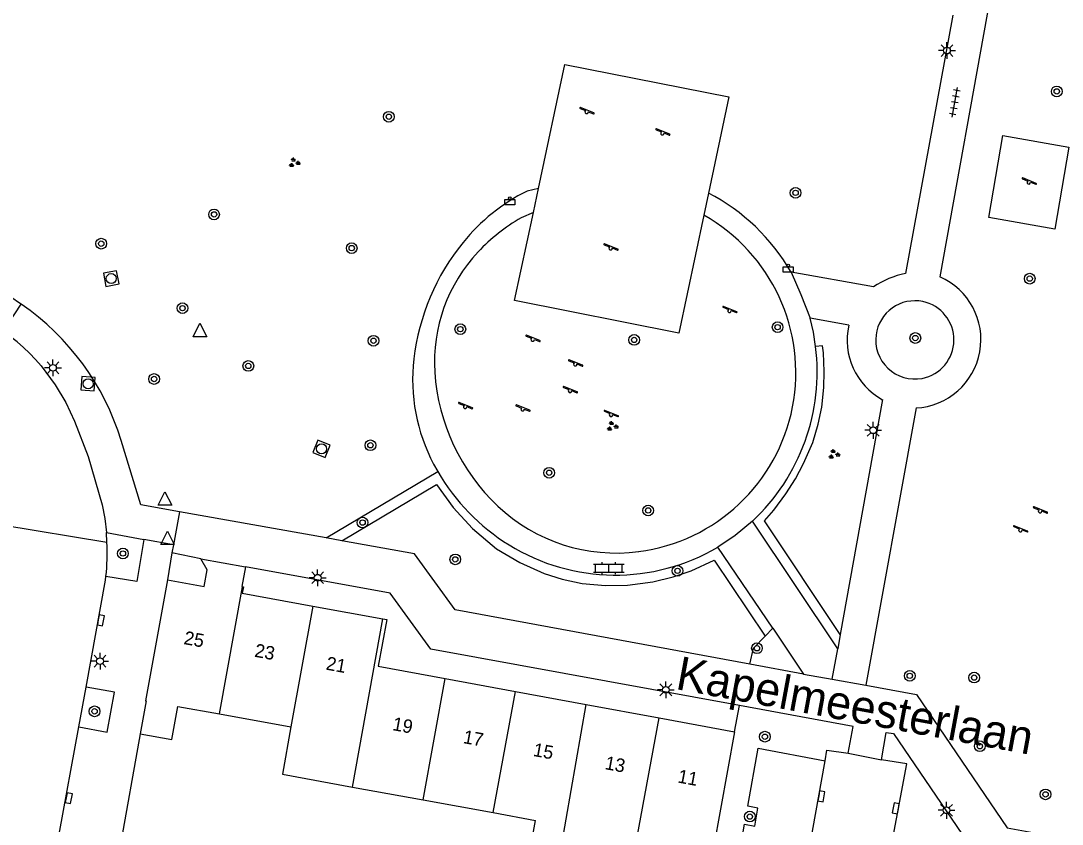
# Model space of a CAD drawing. Extents: x 133000 to 136000, y 400500 to 403500.
# Drawn here: x 133622.8 to 133700.5, y 400549.9 to 400609.9 of the extents above; entities that cross this region are included whole.
import ezdxf

# ---------------------------------------------------------------- set-up
doc = ezdxf.new("R2010")
doc.units = 0
for name, color, linetype in [('gg-afsc-muur', 7, 'Continuous'), ('gg-anno-huisnummerreeks BGT', 7, 'Continuous'), ('gg-anno-openbare ruimte label', 7, 'Continuous'), ('gg-bbg-gedigitaliseerde bebouwing', 7, 'Continuous'), ('gg-bbg-hoofdgebouw', 7, 'Continuous'), ('gg-bbg-tussenscheiding', 7, 'Continuous'), ('gg-knt-onverhard', 7, 'Continuous'), ('gg-knt-verharding', 7, 'Continuous'), ('gg-knt-verharding nz', 7, 'Continuous'), ('gt-grn-groengrens', 7, 'Continuous'), ('gt-grn-weggrens', 7, 'Continuous'), ('gt-symb-afvalbak', 7, 'Continuous'), ('gt-symb-boom', 7, 'Continuous'), ('gt-symb-groenvak', 7, 'Continuous'), ('gt-symb-klinker verharding', 7, 'Continuous'), ('gt-symb-kolk', 7, 'Continuous'), ('gt-symb-lichtmast', 7, 'Continuous'), ('gt-symb-rioolschacht', 7, 'Continuous'), ('gt-symb-speelvoorziening', 7, 'Continuous'), ('gt-symb-tegel verharding', 7, 'Continuous'), ('gt-symb-waterafsluiter', 7, 'Continuous')]:
    doc.layers.add(name, color=color, linetype=linetype)

# ---------------------------------------------------------------- blocks, each defined once
blk = doc.blocks.new('gt0-BOOM')
at = {"layer": 'gt-symb-boom'}
for radius in [0.4, 0.2]:
    blk.add_circle((0, 0), radius, dxfattribs=at)
blk = doc.blocks.new('gt0-SV')
at = {"layer": 'gt-symb-speelvoorziening'}
for p, q in [((-0.477, 0.255), (-0.08, 0.096)), ((0.542, -0.076), (-0.449, 0.324)), ((0.125, 0.014), (0.515, -0.143))]:
    blk.add_line(p, q, dxfattribs=at)
for centre, radius, start, end in [((-0.466, 0.291), 0.0369, 63.6251, 252.66016), ((-0.002, -0.005), 0.128, 127.68665, 8.59861), ((0.531, -0.111), 0.0363, 243.50852, 72.54358)]:
    blk.add_arc(centre, radius, start, end, dxfattribs=at)
blk = doc.blocks.new('gt0-LMAST')
at = {"layer": 'gt-symb-lichtmast'}
for p, q in [((-0.182, 0.173), (-0.447, 0.438)), ((-0.005, 0.246), (-0.005, 0.621)), ((0.172, 0.173), (0.437, 0.438)), ((-0.255, -0.004), (-0.63, -0.004)), ((-0.182, -0.181), (-0.447, -0.446)), ((-0.005, -0.254), (-0.005, -0.629)), ((0.437, -0.446), (0.172, -0.181)), ((0.245, -0.004), (0.62, -0.004))]:
    blk.add_line(p, q, dxfattribs=at)
blk.add_circle((-0.005, -0.004), 0.25, dxfattribs=at)
blk = doc.blocks.new('gt0-TEG1')
at = {"layer": 'gt-symb-tegel verharding'}
for p, q in [((-1.125, 0), (1.125, 0)), ((-0.9, -0.25), (-0.9, 0.25)), ((-0.45, -0.25), (-0.45, 0.25)), ((0, -0.25), (0, 0.25)), ((0.45, -0.25), (0.45, 0.25)), ((0.9, -0.25), (0.9, 0.25))]:
    blk.add_line(p, q, dxfattribs=at)
blk = doc.blocks.new('gt0-GRVAK')
at = {"layer": 'gt-symb-groenvak'}
for p, q in [((-0.11, 0.189), (-0.228, 0.24)), ((-0.182, 0.153), (0.088, 0.153)), ((-0.091, 0.211), (-0.156, 0.322)), ((-0.047, 0.214), (-0.047, 0.393)), ((-0.004, 0.211), (0.061, 0.322)), ((0.015, 0.189), (0.133, 0.24)), ((0.262, -0.052), (0.197, 0.059)), ((0.305, -0.049), (0.305, 0.13)), ((0.349, -0.052), (0.414, 0.059)), ((-0.245, -0.228), (-0.363, -0.177)), ((-0.318, -0.264), (-0.047, -0.264)), ((-0.226, -0.206), (-0.291, -0.095)), ((-0.183, -0.203), (-0.183, -0.024)), ((-0.139, -0.206), (-0.074, -0.095)), ((-0.12, -0.228), (-0.002, -0.177)), ((0.243, -0.074), (0.125, -0.023)), ((0.17, -0.11), (0.441, -0.11)), ((0.368, -0.074), (0.486, -0.023))]:
    blk.add_line(p, q, dxfattribs=at)
blk = doc.blocks.new('gt0-KOLK')
at = {"layer": 'gt-symb-kolk'}
blk.add_lwpolyline([(0, 0), (0.375, 0), (0.375, 0.4), (-0.375, 0.4), (-0.375, 0), (0, 0)], dxfattribs=at)
blk = doc.blocks.new('gt0-ABAK')
at = {"layer": 'gt-symb-afvalbak'}
blk.add_lwpolyline([(0.375, -0.5), (-0.375, -0.5), (-0.375, -0.1), (0.375, -0.1)], close=True, dxfattribs=at)
blk.add_circle((0, 0), 0.1, dxfattribs=at)
blk = doc.blocks.new('gt0-KL1')
at = {"layer": 'gt-symb-klinker verharding'}
for p, q in [((-1.15, 0.3), (1.15, 0.3)), ((-1, -0.3), (-1, 0.3)), ((-0.5, 0.3), (-0.5, 0.45)), ((0, -0.3), (0, 0.3)), ((0.5, 0.3), (0.5, 0.45)), ((1, -0.3), (1, 0.3)), ((-1.15, -0.3), (1.15, -0.3)), ((-0.5, -0.45), (-0.5, -0.3)), ((0.5, -0.45), (0.5, -0.3))]:
    blk.add_line(p, q, dxfattribs=at)
blk = doc.blocks.new('gt0-RS')
at = {"layer": 'gt-symb-rioolschacht'}
blk.add_lwpolyline([(-0.5, -0.5), (0.5, -0.5), (0.5, 0.5), (-0.5, 0.5)], close=True, dxfattribs=at)
blk.add_circle((0, 0), 0.375, dxfattribs=at)
blk = doc.blocks.new('gt0-WAFSL')
at = {"layer": 'gt-symb-waterafsluiter'}
for p, q in [((-0.5, -0.333), (0, 0.667)), ((0, 0.667), (0.5, -0.333)), ((0.5, -0.333), (-0.5, -0.333))]:
    blk.add_line(p, q, dxfattribs=at)

msp = doc.modelspace()

# ---------------------------------------------------------------- linework, layer by layer
at = {"layer": 'gg-afsc-muur'}
for p, q in [((133634.08, 400570.17), (133633.76, 400568.16)), ((133631.709, 400556.671), (133630.137, 400547.881))]:
    msp.add_line(p, q, dxfattribs=at)
at = {"layer": 'gg-bbg-gedigitaliseerde bebouwing'}
for p, q in [((133634.532, 400558.708), (133637.624, 400558.157)), ((133637.624, 400558.157), (133642.966, 400557.205)), ((133647.558, 400552.7), (133652.819, 400551.743)), ((133652.819, 400551.743), (133658.058, 400550.79)), ((133658.058, 400550.79), (133661.212, 400550.216))]:
    msp.add_line(p, q, dxfattribs=at)
msp.add_lwpolyline([(133642.966, 400557.205), (133642.335, 400553.661), (133647.558, 400552.7)], dxfattribs=at)
at = {"layer": 'gg-bbg-hoofdgebouw'}
for p, q in [((133636.23, 400569.73), (133639.58, 400569.14)), ((133644.605, 400566.205), (133649.818, 400565.263)), ((133654.474, 400560.799), (133659.734, 400559.833)), ((133659.734, 400559.833), (133665.008, 400558.864)), ((133665.008, 400558.864), (133670.442, 400557.866)), ((133670.442, 400557.866), (133676.08, 400556.83)), ((133676.08, 400556.83), (133674.467, 400547.959))]:
    msp.add_line(p, q, dxfattribs=at)
for points in [[(133633.76, 400568.16), (133636.48, 400567.66), (133636.71, 400568.91), (133636.23, 400569.73)], [(133639.58, 400569.14), (133639.3, 400567.651), (133639.358, 400567.64)], [(133633.76, 400568.16), (133632.11, 400559.14), (133632.159, 400559.131), (133631.709, 400556.671)], [(133639.358, 400567.64), (133639.41, 400567.63), (133639.32, 400567.16), (133644.605, 400566.205)], [(133649.818, 400565.263), (133650.11, 400565.21), (133649.46, 400561.72), (133654.474, 400560.799)], [(133631.709, 400556.671), (133634.08, 400556.237), (133634.532, 400558.708)], [(133662.766, 400546.131), (133660.552, 400546.528), (133661.212, 400550.216)]]:
    msp.add_lwpolyline(points, dxfattribs=at)
at = {"layer": 'gg-bbg-tussenscheiding'}
for p, q in [((133637.624, 400558.157), (133639.358, 400567.64)), ((133644.605, 400566.205), (133642.966, 400557.205)), ((133647.558, 400552.7), (133649.818, 400565.263)), ((133652.819, 400551.743), (133654.474, 400560.799)), ((133658.058, 400550.79), (133659.734, 400559.833)), ((133662.766, 400546.131), (133665.008, 400558.864)), ((133668.78, 400548.84), (133670.442, 400557.866))]:
    msp.add_line(p, q, dxfattribs=at)
at = {"layer": 'gg-knt-onverhard'}
for points in [[(133661.433, 400597.346), (133663.401, 400606.609), (133675.642, 400604.196), (133674.122, 400597.016)], [(133673.773, 400595.365), (133671.909, 400586.559), (133659.658, 400588.991), (133661.055, 400595.566)]]:
    msp.add_lwpolyline(points, dxfattribs=at)
at = {"layer": 'gg-knt-verharding'}
for p, q in [((133697.797, 400626.302), (133691.382, 400590.767)), ((133692.36, 400610.29), (133688.836, 400591.028)), ((133661.433, 400597.346), (133660.585, 400597.162)), ((133661.055, 400595.566), (133661.433, 400597.346)), ((133674.122, 400597.016), (133673.773, 400595.365)), ((133661.055, 400595.566), (133660.137, 400595.174)), ((133686.44, 400590.013), (133680.286, 400591.116)), ((133621.936, 400587.354), (133622.834, 400588.725)), ((133684.597, 400587.156), (133681.71, 400587.677)), ((133687.12, 400581.603), (133683.962, 400564.083)), ((133689.616, 400580.985), (133685.88, 400560.29)), ((133653.61, 400576.782), (133653.917, 400576.232)), ((133645.586, 400571.286), (133634.647, 400573.238)), ((133683.77, 400563.02), (133677.41, 400572.54)), ((133629.232, 400570.974), (133629.186, 400571.683)), ((133629.186, 400571.683), (133631.988, 400571.176)), ((133646.761, 400571.076), (133645.586, 400571.286)), ((133678.925, 400564.545), (133674.83, 400570.61)), ((133636.23, 400569.73), (133634.08, 400570.17)), ((133678.925, 400564.545), (133681.23, 400561.13)), ((133683.962, 400564.083), (133683.77, 400563.02)), ((133681.23, 400561.13), (133677.22, 400561.869)), ((133627.131, 400557.189), (133627.672, 400560.162)), ((133625.674, 400549.187), (133627.131, 400557.189)), ((133677.836, 400555.603), (133682.827, 400554.662)), ((133684.56, 400555.24), (133687.05, 400554.72))]:
    msp.add_line(p, q, dxfattribs=at)
for points in [[(133695.055, 400595.183), (133696.094, 400601.301), (133701.016, 400600.453), (133699.977, 400594.335), (133695.055, 400595.183)], [(133680.286, 400591.116), (133681.018, 400589.437), (133681.71, 400587.677)], [(133682.123, 400585.582), (133681.953, 400586.638), (133681.71, 400587.677)], [(133624.311, 400584.13), (133625.356, 400582.715), (133626.165, 400581.399), (133626.804, 400579.989), (133627.838, 400577.361), (133628.883, 400573.765), (133629.066, 400572.729), (133629.186, 400571.683)], [(133634.647, 400573.238), (133631.77, 400573.751), (133630.289, 400578.564)], [(133677.41, 400572.54), (133676.112, 400571.476), (133674.83, 400570.61)], [(133631.988, 400571.176), (133631.448, 400568.038), (133629.154, 400568.402)], [(133677.22, 400561.869), (133655.23, 400565.92), (133652.18, 400570.11), (133646.761, 400571.076)], [(133676.442, 400558.775), (133653.41, 400563), (133650.38, 400567.17), (133639.58, 400569.14)], [(133627.672, 400560.162), (133629.126, 400568.146), (133629.154, 400568.402)], [(133627.131, 400557.189), (133629.246, 400556.804), (133629.795, 400559.776), (133627.672, 400560.162)], [(133685.88, 400560.29), (133689.64, 400559.61), (133696.42, 400549.65), (133718.848, 400545.574)], [(133684.56, 400555.24), (133684.92, 400557.22), (133676.442, 400558.775)], [(133687.05, 400554.72), (133687.4, 400556.78), (133687.94, 400556.69), (133694.62, 400546.86)], [(133676.417, 400547.599), (133676.823, 400549.932), (133677.584, 400549.78), (133677.808, 400551.129), (133677.062, 400551.267), (133677.836, 400555.603)], [(133682.827, 400554.662), (133682.97, 400555.45), (133684.56, 400555.24)], [(133687.39, 400546.213), (133688.93, 400554.42), (133687.05, 400554.72)]]:
    msp.add_lwpolyline(points, dxfattribs=at)
for centre, radius, start, end in [((133667.054, 400584.197), 14.49, 116.5163, 140.91437), ((133667.202, 400583.616), 15.082, 29.82141, 62.68583), ((133667.28, 400582.889), 14.21, 120.17568, 136.7059), ((133667.177, 400583.622), 13.468, 277.41282, 60.67764), ((133668.92, 400582.676), 16.897, 140.90051, 173.31017), ((133665.662, 400584.414), 11.987, 136.70653, 183.6492), ((133690.293, 400584.253), 6.93, 102.13715, 123.78009), ((133611.924, 400572.894), 19.226, 55.4287, 63.35378), ((133689.354, 400586.083), 5.105, 272.94586, 66.58674), ((133613.564, 400575.122), 14.023, 39.97011, 81.01857), ((133611.929, 400572.909), 19.211, 17.11988, 55.41419), ((133689.527, 400586.06), 2.92, 78.35316, 172.33223), ((133689.526, 400586.061), 2.919, 280.64289, 78.33685), ((133689.514, 400586.04), 5.042, 167.21803, 241.65122), ((133689.526, 400586.061), 2.919, 172.33838, 280.64136), ((133666.979, 400583.682), 15.263, 313.11228, 7.15095), ((133665.503, 400583.078), 13.457, 173.3153, 207.89409), ((133668.682, 400584.605), 15.013, 183.64169, 226.80142), ((133667.534, 400584.176), 15.765, 210.25844, 238.2653), ((133667.249, 400583.079), 12.92, 226.80569, 277.41048), ((133611.652, 400570.22), 17.596, 354.06982, 2.45607), ((133667.167, 400583.594), 15.077, 238.28917, 300.54937)]:
    msp.add_arc(centre, radius, start, end, dxfattribs=at)
at = {"layer": 'gg-knt-verharding nz'}
msp.add_line((133679.271, 400534.991), (133682.827, 400554.662), dxfattribs=at)
at = {"layer": 'gt-grn-groengrens'}
for p, q in [((133645.586, 400571.286), (133653.917, 400576.232)), ((133678.367, 400563.966), (133678.925, 400564.545)), ((133676.08, 400556.83), (133676.442, 400558.775))]:
    msp.add_line(p, q, dxfattribs=at)
for points in [[(133683.962, 400564.083), (133678.304, 400572.552), (133679.004, 400573.35), (133679.9, 400574.576), (133680.614, 400575.705), (133681.22, 400576.831), (133681.914, 400578.411), (133682.322, 400579.778), (133682.578, 400581.032), (133682.745, 400582.518), (133682.772, 400583.711), (133682.715, 400585.094), (133682.641, 400585.624), (133682.123, 400585.582)], [(133646.761, 400571.076), (133653.822, 400575.268), (133655.061, 400573.554), (133656.511, 400571.985), (133658.301, 400570.481), (133660.034, 400569.443), (133661.873, 400568.641), (133663.211, 400568.21), (133664.708, 400567.88), (133666.441, 400567.738), (133668.092, 400567.762), (133669.978, 400568.01), (133671.493, 400568.376), (133672.837, 400568.836), (133674.548, 400569.623), (133678.367, 400563.966)], [(133677.22, 400561.869), (133677.489, 400563.054), (133678.367, 400563.966)]]:
    msp.add_lwpolyline(points, dxfattribs=at)
at = {"layer": 'gt-grn-weggrens'}
for p, q in [((133634.647, 400573.238), (133634.191, 400570.769)), ((133621.386, 400572.275), (133629.232, 400570.974)), ((133634.191, 400570.769), (133631.988, 400571.176)), ((133634.191, 400570.769), (133634.08, 400570.17)), ((133683.359, 400560.745), (133683.77, 400563.02)), ((133681.23, 400561.13), (133683.359, 400560.745)), ((133683.359, 400560.745), (133685.88, 400560.29))]:
    msp.add_line(p, q, dxfattribs=at)

# ---------------------------------------------------------------- block references
at = {"layer": 'gt-symb-afvalbak'}
for p in [(133659.29, 400596.642), (133680.073, 400591.613)]:
    msp.add_blockref('gt0-ABAK', p, dxfattribs=at)
at = {"layer": 'gt-symb-boom'}
for p in [(133700.122, 400604.6), (133650.269, 400602.712), (133680.625, 400597.033), (133637.223, 400595.424), (133628.802, 400593.243), (133647.497, 400592.909), (133698.101, 400590.632), (133634.867, 400588.43), (133655.605, 400586.861), (133679.286, 400587.014), (133649.122, 400585.999), (133668.577, 400586.06), (133689.564, 400586.202), (133639.78, 400584.119), (133632.749, 400583.144), (133648.892, 400578.199), (133662.233, 400576.149), (133669.625, 400573.336), (133648.305, 400572.435), (133630.421, 400570.126), (133655.228, 400569.686), (133671.813, 400568.831), (133677.744, 400563.057), (133689.15, 400560.999), (133693.957, 400560.866), (133628.306, 400558.349), (133678.337, 400556.458), (133694.378, 400555.747), (133699.283, 400552.154), (133677.212, 400550.498)]:
    msp.add_blockref('gt0-BOOM', p, dxfattribs=at)
at = {"layer": 'gt-symb-groenvak'}
for p in [(133643.199, 400599.281), (133666.937, 400579.616), (133683.483, 400577.525)]:
    msp.add_blockref('gt0-GRVAK', p, dxfattribs=at)
at = {"layer": 'gt-symb-klinker verharding'}
msp.add_blockref('gt0-KL1', (133666.687, 400569.024), dxfattribs=at)
at = {"layer": 'gt-symb-kolk'}
for p, rotation in [((133628.581, 400565.177), -100.19720557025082), ((133626.189, 400551.904), -100.36632260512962), ((133682.35, 400552.046), -100.25359802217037), ((133688.299, 400551.075), 79.39794170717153)]:
    msp.add_blockref('gt0-KOLK', p, dxfattribs=dict(at, rotation=rotation))
at = {"layer": 'gt-symb-lichtmast'}
for p in [(133691.932, 400607.649), (133625.206, 400583.982), (133686.42, 400579.321), (133644.961, 400568.323), (133628.716, 400562.096), (133670.952, 400559.959), (133691.892, 400550.97)]:
    msp.add_blockref('gt0-LMAST', p, dxfattribs=at)
at = {"layer": 'gt-symb-rioolschacht'}
for p, rotation in [((133629.549, 400590.639), -169.74640197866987), ((133627.824, 400582.793), -94.18770451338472), ((133645.248, 400577.934), 157.48588735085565)]:
    msp.add_blockref('gt0-RS', p, dxfattribs=dict(at, rotation=rotation))
at = {"layer": 'gt-symb-speelvoorziening'}
for p in [(133665.029, 400603.073), (133670.687, 400601.486), (133698.036, 400597.818), (133666.819, 400592.908), (133675.688, 400588.238), (133661.004, 400586.084), (133664.184, 400584.252), (133663.783, 400582.265), (133655.96, 400581.074), (133660.251, 400580.884), (133666.848, 400580.479), (133698.872, 400573.287), (133697.402, 400571.875)]:
    msp.add_blockref('gt0-SV', p, dxfattribs=at)
at = {"layer": 'gt-symb-tegel verharding', "rotation": 79.74640197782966}
msp.add_blockref('gt0-TEG1', (133692.511, 400603.784), dxfattribs=at)
at = {"layer": 'gt-symb-waterafsluiter'}
for p in [(133636.173, 400586.635), (133633.56, 400574.056), (133633.742, 400571.131)]:
    msp.add_blockref('gt0-WAFSL', p, dxfattribs=at)

# ---------------------------------------------------------------- texts
at = {"layer": 'gg-anno-huisnummerreeks BGT'}
for s, rotation, p in [('25', 349.6, (133634.916, 400563.374)), ('23', 349.7, (133640.193, 400562.43)), ('21', 349.7, (133645.524, 400561.467)), ('19', 349.6, (133650.488, 400556.955)), ('17', 349.6, (133655.764, 400555.986)), ('15', 349.6, (133660.991, 400555.026)), ('13', 349.6, (133666.345, 400554.043)), ('11', 349.6, (133671.777, 400553.045))]:
    msp.add_text(s, height=1, rotation=rotation, dxfattribs=at).set_placement(p)
at = {"layer": 'gg-anno-openbare ruimte label'}
msp.add_text('Kapelmeesterlaan', height=2.5, rotation=349.5, dxfattribs=at).set_placement((133671.598, 400560.023))

doc.saveas('drawing.dxf')
